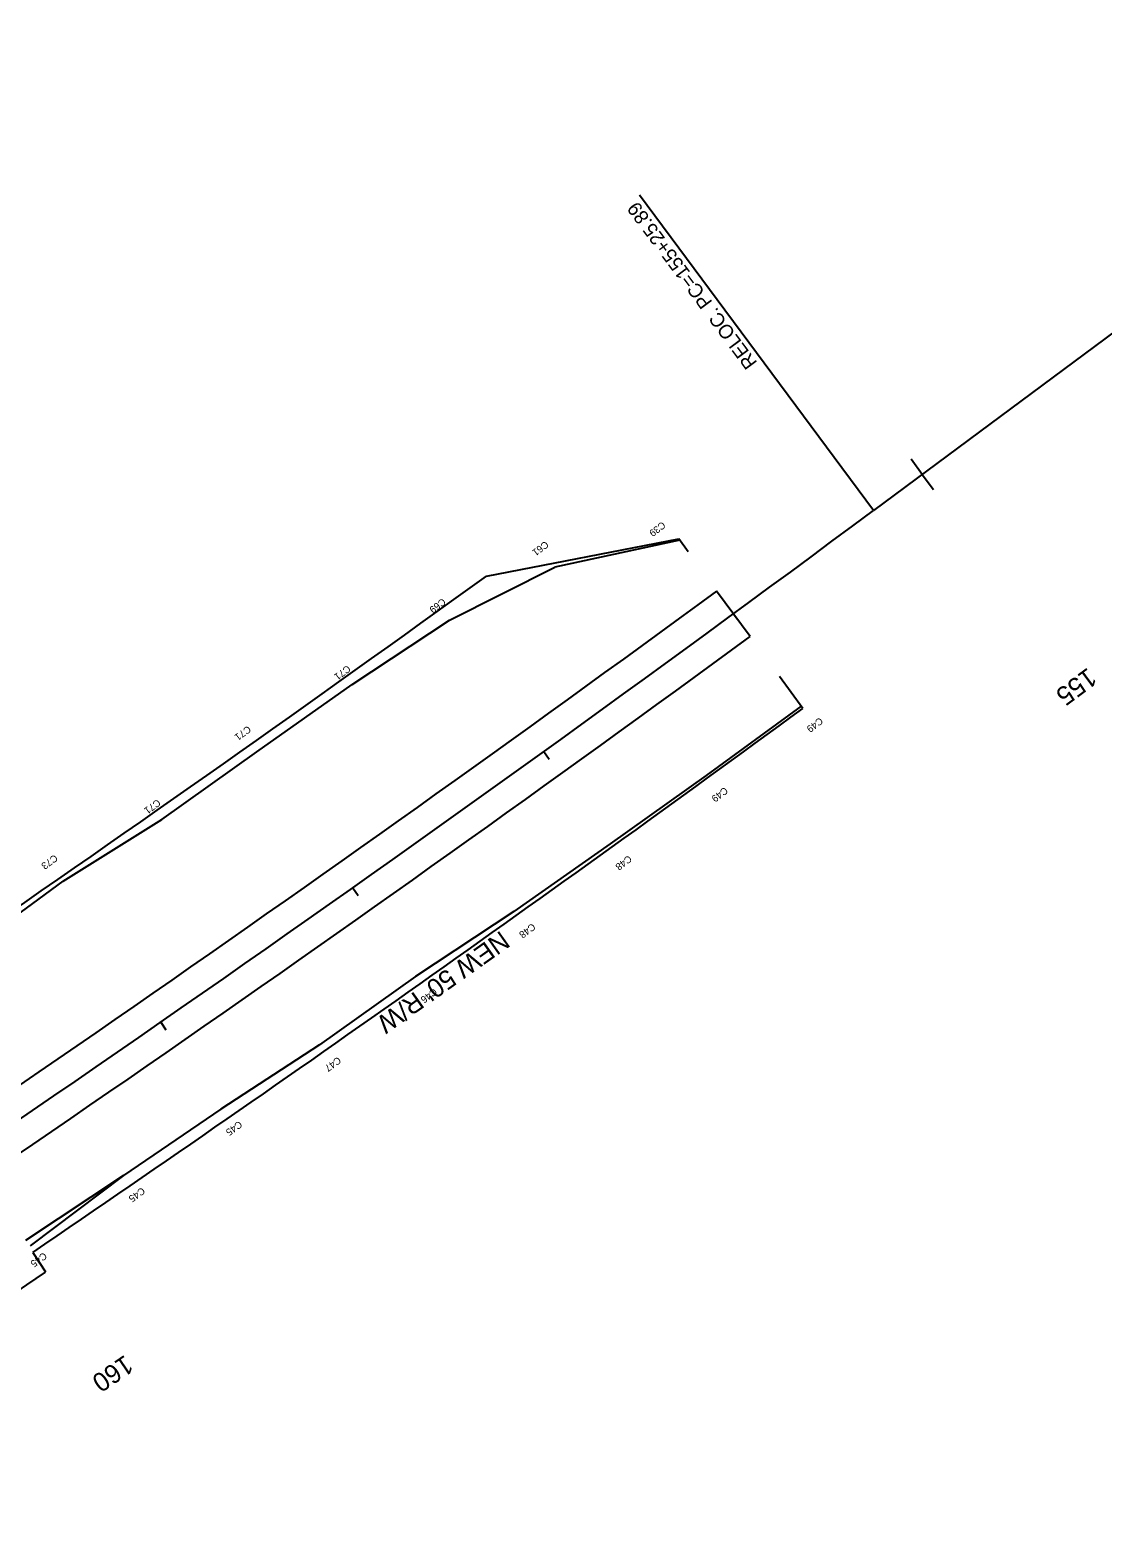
# Model space of a CAD drawing. Extents: x 1469024 to 1473560, y 1105695 to 1109739.
# Drawn here: x 1471886 to 1472343, y 1108042 to 1108684 of the extents above; entities that cross this region are included whole.
import ezdxf

# ---------------------------------------------------------------- set-up
doc = ezdxf.new("R2010")
doc.units = 0
for name, color, linetype in [('RD_HC_CL_Rel', 7, 'Continuous'), ('RD_HC_Data_Rel', 7, 'Continuous'), ('RD_HC_Data_Tic_Rel', 7, 'Continuous'), ('RD_HC_TX_Rel_Sta50', 7, 'Continuous'), ('RD_PD_CstnLmt', 7, 'Continuous'), ('RD_PD_CstnLmt_TX', 7, 'Continuous'), ('RD_PD_DR_ErosCtrl', 7, 'Continuous'), ('RD_PD_Final_TrvlWay', 7, 'Continuous'), ('RD_PD_RW', 7, 'Continuous'), ('RD_PD_RW_TX', 7, 'Continuous')]:
    doc.layers.add(name, color=color, linetype=linetype)

msp = doc.modelspace()

# ---------------------------------------------------------------- linework, layer by layer
at = {"layer": 'RD_HC_CL_Rel'}
msp.add_line((1472703.34, 1108819.72), (1472245.26, 1108479.63), dxfattribs=at)
msp.add_arc((1465390.13, 1117713.11), 11500, 303.079489, 306.590952, dxfattribs=at)
at = {"layer": 'RD_HC_Data_Rel'}
msp.add_line((1472245.26, 1108479.63), (1472145.44, 1108614.08), dxfattribs=at)
at = {"layer": 'RD_HC_Data_Tic_Rel'}
for p, q in [((1472266.04, 1108495.06), (1472261.28, 1108501.49)), ((1472266.04, 1108495.06), (1472270.81, 1108488.64)), ((1472185.61, 1108435.65), (1472187.16, 1108433.53)), ((1472104.68, 1108376.91), (1472107.02, 1108373.66)), ((1472023.24, 1108318.87), (1472025.55, 1108315.6)), ((1471941.31, 1108261.55), (1471943.58, 1108258.26))]:
    msp.add_line(p, q, dxfattribs=at)
at = {"layer": 'RD_PD_CstnLmt'}
for p, q in [((1472162.68, 1108466.95), (1472109.4, 1108455.52)), ((1472064.44, 1108432.86), (1472109.4, 1108455.52)), ((1472022.93, 1108405.47), (1472064.44, 1108432.86)), ((1471982.38, 1108376.74), (1472022.93, 1108405.47)), ((1472214.42, 1108396.31), (1472173.89, 1108366.67)), ((1471941.84, 1108348), (1471982.38, 1108376.74)), ((1472173.89, 1108366.67), (1472132.95, 1108337.61)), ((1471899.66, 1108321.63), (1471941.84, 1108348)), ((1472132.95, 1108337.61), (1472091.91, 1108308.67)), ((1471859.64, 1108292.15), (1471899.66, 1108321.63)), ((1472091.91, 1108308.67), (1472049.97, 1108281.03)), ((1472049.97, 1108281.03), (1472009.1, 1108251.87)), ((1472009.1, 1108251.87), (1471966.95, 1108224.55)), ((1471966.95, 1108224.55), (1471925.51, 1108196.23))]:
    msp.add_line(p, q, dxfattribs=at)
msp.add_lwpolyline([(1471925.51, 1108196.23), (1471883.66, 1108168.5)], dxfattribs=at)
at = {"layer": 'RD_PD_DR_ErosCtrl'}
msp.add_line((1471925.51, 1108196.23), (1471885.65, 1108166.25), dxfattribs=at)
at = {"layer": 'RD_PD_Final_TrvlWay'}
msp.add_line((1472192.7, 1108425.96), (1472178.4, 1108445.23), dxfattribs=at)
for radius in [11488, 11512]:
    msp.add_arc((1465390.13, 1117713.11), radius, 303.079489, 306.221713, dxfattribs=at)
at = {"layer": 'RD_PD_RW'}
for p, q in [((1472080.22, 1108451.73), (1472162.26, 1108467.53)), ((1472166.25, 1108462.08), (1472162.26, 1108467.53)), ((1472215.16, 1108395.31), (1472205.25, 1108408.83)), ((1471886.76, 1108163.44), (1471892.26, 1108155.09))]:
    msp.add_line(p, q, dxfattribs=at)
for radius, start, end in [(11425, 303.079489, 305.842989), (11550, 304.227384, 306.221713), (11560, 302.674208, 304.226672)]:
    msp.add_arc((1465390.13, 1117713.11), radius, start, end, dxfattribs=at)

# ---------------------------------------------------------------- texts
at = {"layer": 'RD_HC_Data_Rel'}
msp.add_text('RELOC. PC=155+25.89', height=6, rotation=126.59095, dxfattribs=at).set_placement((1472195.96, 1108542.67))
at = {"layer": 'RD_HC_TX_Rel_Sta50'}
for s, rotation, p in [('155', 216.59095, (1472336.67, 1108412.99)), ('160', 214.22882, (1471926.07, 1108120.03))]:
    msp.add_text(s, height=8, rotation=rotation, dxfattribs=at).set_placement(p)
at = {"layer": 'RD_PD_CstnLmt_TX'}
for s, rotation, p in [('C39', 217.73316, (1472155.13, 1108475.15)), ('C61', 217.48405, (1472105.29, 1108466.86)), ('C69', 217.23493, (1472061.46, 1108442.45)), ('C71', 216.98582, (1472020.88, 1108413.91)), ('C71', 216.73671, (1471978.42, 1108388.13)), ('C49', 217.73316, (1472222.3, 1108391.67)), ('C49', 217.48405, (1472181.75, 1108361.99)), ('C71', 216.4876, (1471939.88, 1108356.8)), ('C73', 216.23848, (1471896.02, 1108333.21)), ('C48', 217.23493, (1472140.78, 1108332.89)), ('C48', 216.98582, (1472099.73, 1108303.92)), ('C46', 216.73671, (1472057.76, 1108276.24)), ('C47', 216.4876, (1472016.85, 1108247.03)), ('C45', 216.23848, (1471974.7, 1108219.7)), ('C45', 216.23848, (1471933.27, 1108191.37)), ('C45', 216.23848, (1471891.42, 1108163.65))]:
    msp.add_text(s, height=3, rotation=rotation, dxfattribs=at).set_placement(p)
at = {"layer": 'RD_PD_RW_TX'}
msp.add_text("NEW 50' R/W", height=8, rotation=215.298, dxfattribs=at).set_placement((1472086.34, 1108300.83))

doc.saveas('drawing.dxf')
